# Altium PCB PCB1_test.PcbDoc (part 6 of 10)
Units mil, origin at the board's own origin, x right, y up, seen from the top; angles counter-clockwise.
Board outline 6690 x 6690 mil, 6 copper layers (Layer 1 - Top Layer, Layer 2 - GND, Layer 3 - PWR, Layer 4 - Signal, Layer 5 - GND, Layer 6 - Bottom Layer), stack 80.244 mil thick; 821 components, 458 nets, 3752 pads, 1525 vias.
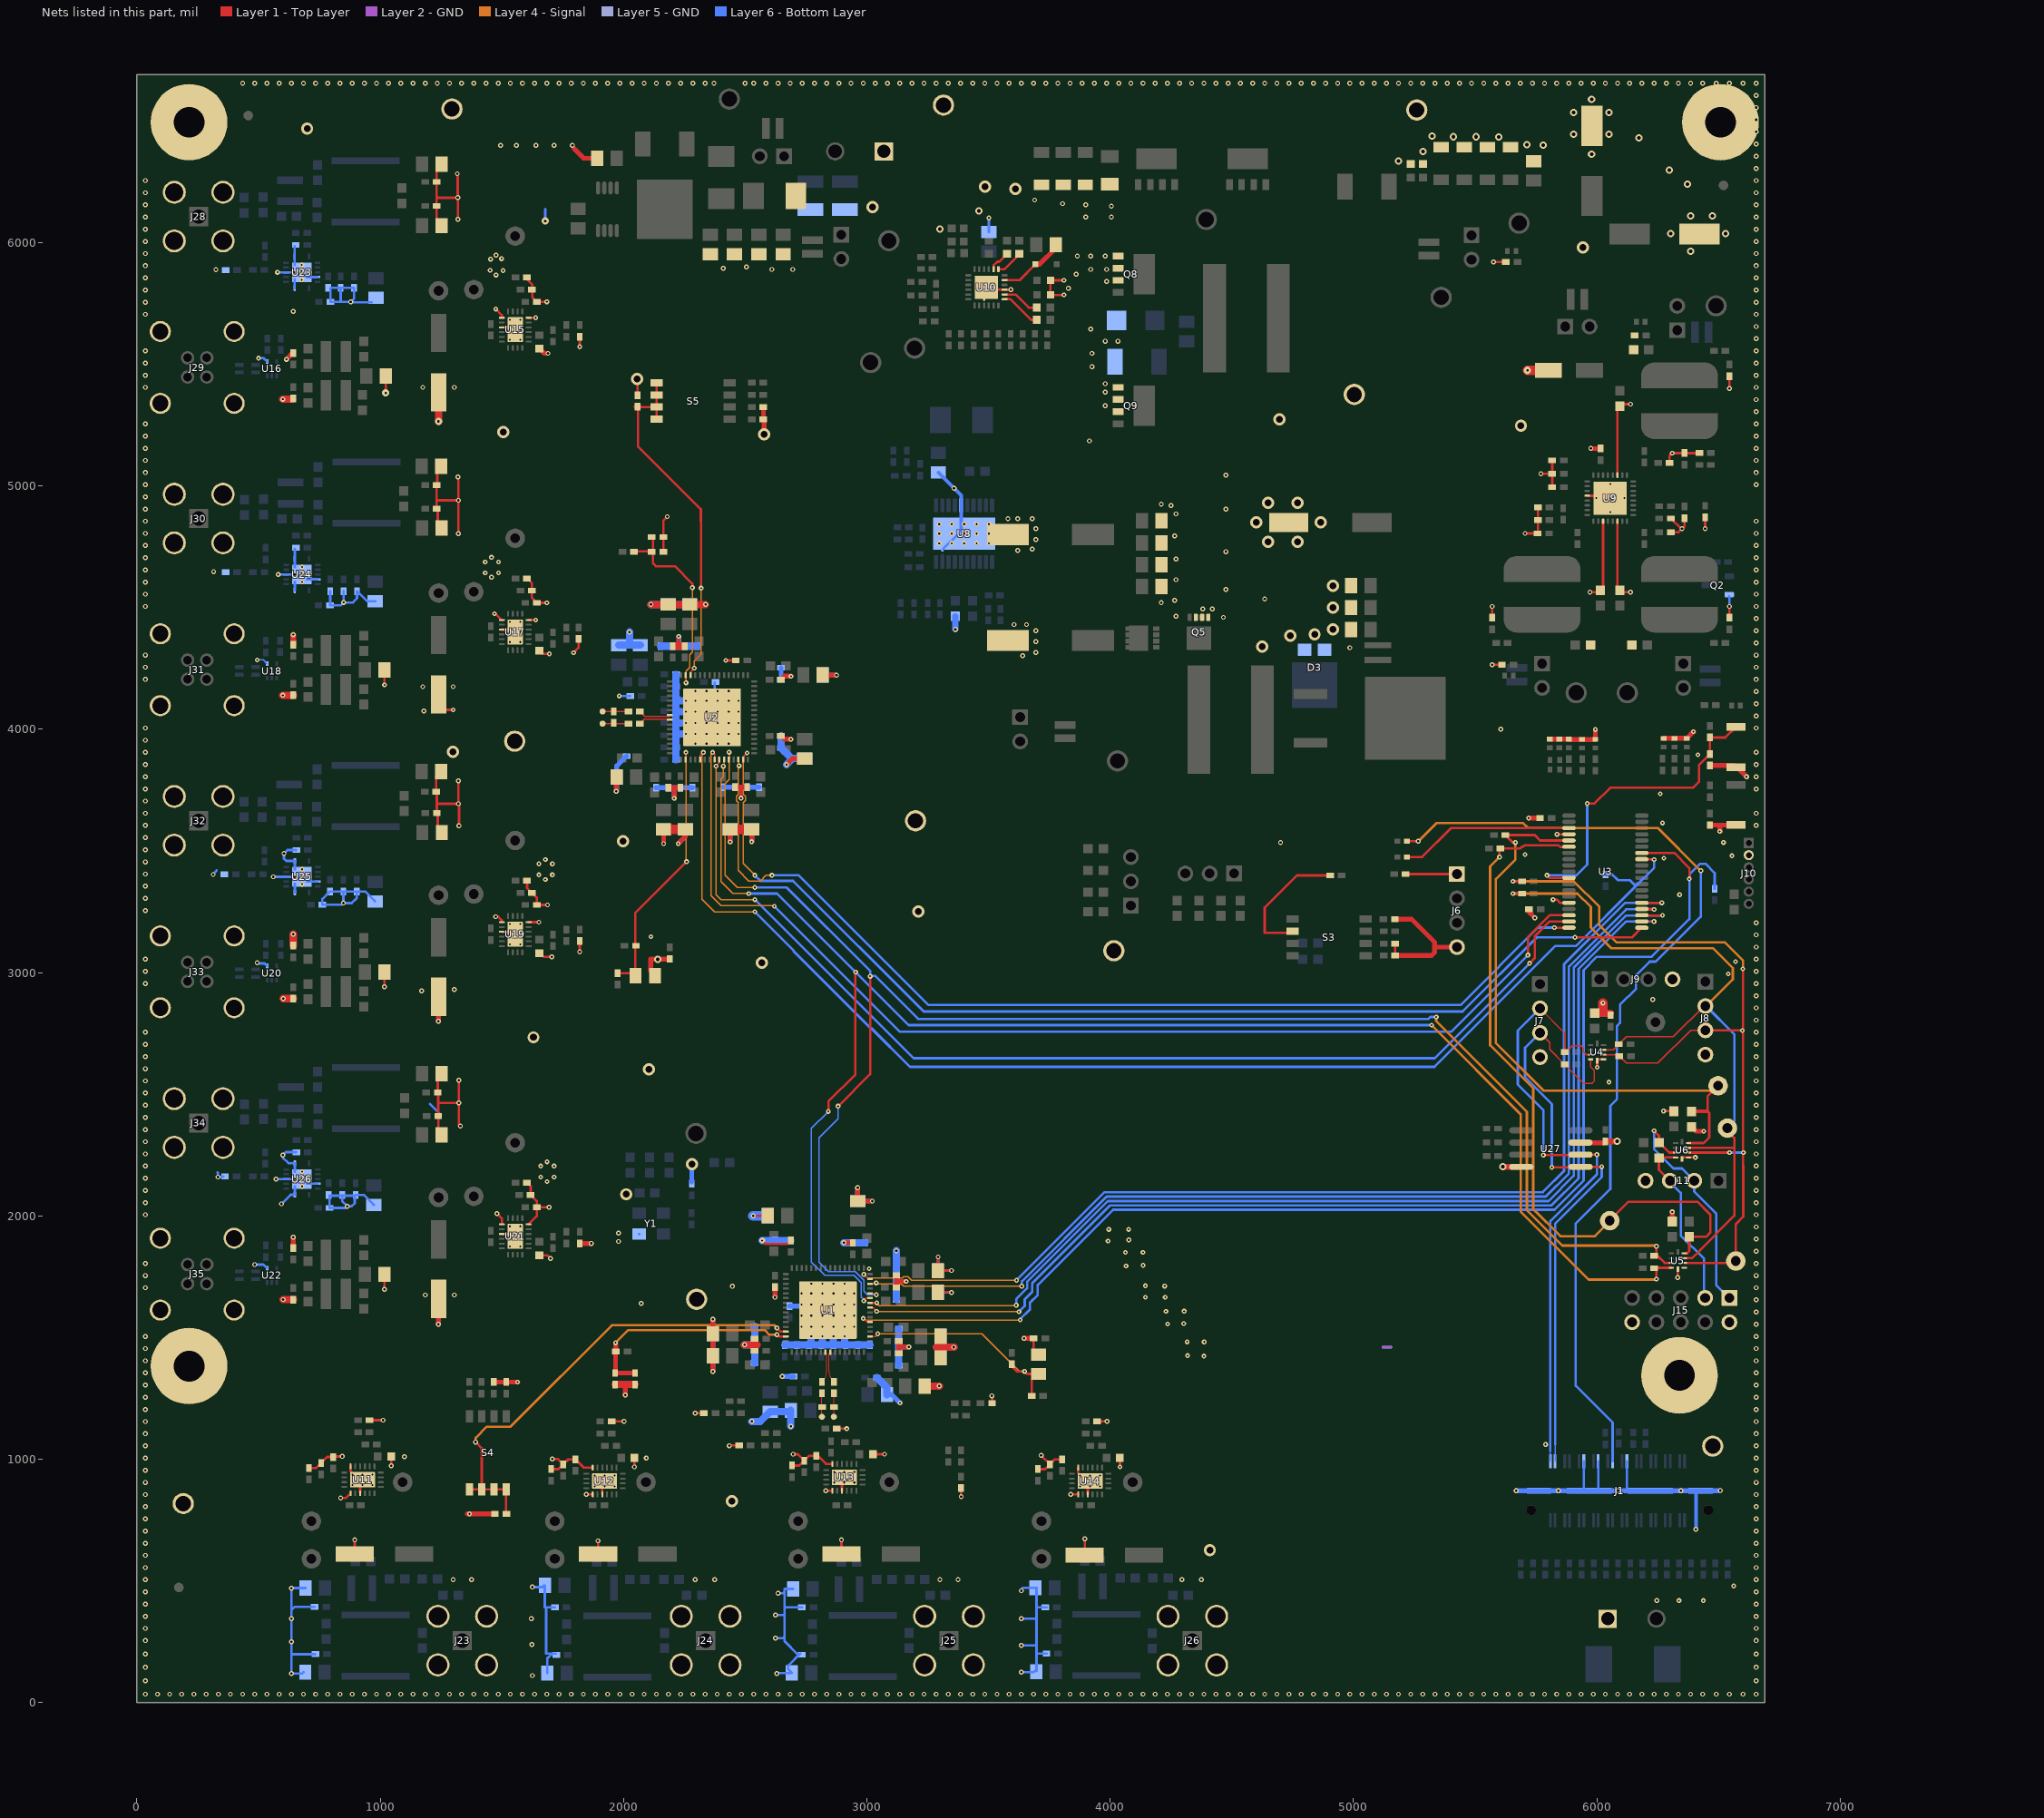
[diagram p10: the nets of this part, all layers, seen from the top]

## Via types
v1: diameter 20, hole 10, Layer 1 - Top Layer to Layer 6 - Bottom Layer, tented both sides, 491 vias
v2: diameter 20, hole 10, Layer 1 - Top Layer to Layer 6 - Bottom Layer, 310 vias
v3: diameter 19.68, hole 7.87, Layer 1 - Top Layer to Layer 6 - Bottom Layer, 274 vias
v4: diameter 19.68, hole 7.87, Layer 1 - Top Layer to Layer 6 - Bottom Layer, tented both sides, 217 vias
v5: diameter 50, hole 28, Layer 1 - Top Layer to Layer 6 - Bottom Layer, 101 vias
v6: diameter 30, hole 15, Layer 1 - Top Layer to Layer 6 - Bottom Layer, 73 vias
v7: diameter 22, hole 10, Layer 1 - Top Layer to Layer 6 - Bottom Layer, 36 vias
v8: diameter 30, hole 10, Layer 1 - Top Layer to Layer 6 - Bottom Layer, 14 vias
v9: diameter 19.68, hole 7.87, Layer 1 - Top Layer to Layer 6 - Bottom Layer, tented bottom, 4 vias
v10: diameter 30, hole 10, Layer 1 - Top Layer to Layer 6 - Bottom Layer, tented both sides, 2 vias
v11: diameter 40, hole 10, Layer 1 - Top Layer to Layer 6 - Bottom Layer, 1 vias
v12: diameter 23.62, hole 7.87, Layer 1 - Top Layer to Layer 6 - Bottom Layer, tented both sides, 1 vias
v13: diameter 23.62, hole 7.87, Layer 1 - Top Layer to Layer 6 - Bottom Layer, 1 vias

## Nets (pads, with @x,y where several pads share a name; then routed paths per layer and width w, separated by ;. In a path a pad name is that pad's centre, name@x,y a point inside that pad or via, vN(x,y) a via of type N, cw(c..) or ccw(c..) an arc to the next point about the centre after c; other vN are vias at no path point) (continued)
GND: C1.2 C2.2 C3.2 C4.2 C5.2 C6.2 C7.2 C8.2 C9.2 C10.2 C11.2 C12.2 C13.2 C14.2 C15.2 C16.2 C17.2 C18.2 C19.2 C20.2 C21.2 C22.2 C23.2 C24.2 C25.2 C26.2 C27.2 C28.2 C29.2 C30.2 C31.2 C32.2 C33.2 C34.2 C36.2 C37.2 C38.2 C39.2 C40.2 C42.2 C43.2 C44.2 C45.2 C46.2 C47.2 C48.2 C49.2 C50.2 C51.2 C52.2 C53.2 C54.2 C55.2 C56.2 C57.2 C58.2 C59.2 C60.2 C61.2 C62.2 C63.2 C64.2 C65.2 C66.2 C67.2 C68.2 C69.2 C70.2 C71.2 C72.2 C73.2 C74.2 C75.2 C76.2 C77.2 C78.2 C79.2 C80.2 C81.2 C82.2 C83.2 C84.2 C85.2 C86.2 C87.2 C88.2 C89.2 C90.2 C91.2 C92.2 C93.2 C94.2 C95.2 C96.2 C97.2 C98.2 C99.2 C100.2 C103.2 C104.2 C105.2 C106.2 C107.2 C108.2 C109.2 C110.2 C111.2 C112.2 C113.2 C114.2 C115.2 C116.2 C117.2 C118.2 C119.2 C120.2 C121.2 C122.2 C123.2 C124.2 C125.2 C126.2 C127.2 C128.2 C129.2 C130.2 C131.2 C132.2 C133.2 C134.2 C135.2 C136.2 C138.2 C139.2 C140.2 C141.2 C142.2 C143.2 C144.2 C145.2 C146.2 C147.2 C148.2 C152.2 C156.2 C157.1 C158.2 C159.1 C161.2 C162.1 C163.1 C165.2 C166.1 C167.2 C168.2 C169.2 C170.2 C171.1 C172.2 C173.2 C174.2 C175.2 C179.1 C180.2 C181.1 C183.2 C184.2 C185.2 C186.1 C187.2 C188.2 C189.2 C190.1 C196.2 C197.2 C198.2 C199.2 C200.2 C201.2 C202.2 C203.2 C210.1 C211.1 C212.2 C213.2 C214.2 C215.2 C216.2 C217.2 C218.2 C219.2 C220.2 C221.2 C222.2 C223.2 C230.1 C231.1 C232.2 C233.2 C234.2 C235.2 C236.2 C237.2 C238.2 C239.2 C240.1 C242.2 C243.2 C246.2 C251.2 C252.2 C253.2 C254.2 C255.1 C257.2 C258.2 C261.2 C266.2 C267.2 C268.2 C269.2 C270.1 C272.2 C273.2 C276.2 C281.2 C282.2 C283.2 C284.2 C285.1 C287.2 C288.2 C291.2 C296.2 C297.2 C298.2 C299.2 C300.2 C301.2 C302.2 C303.2 C304.2 C305.2 C306.2 C307.2 C308.2 C309.2 C310.2 C311.2 C312.2 C313.2 C_PVIN1.2 C_PVIN2.2 C_PVIN3.2 C_VIN1.2 D2.1 D3.1 D3.2 D8.2 D11.2 D12.2 D13.1 D15.1 D16.2 D17.2 D18.1 D19.1 H1.1 H2.1 H3.1 H4.1 J1.12 J1.16 J1.24 J1.MP1 J1.MP2 J1.MP3 J1.MP4 J6.4 J7.4 J8.4 J9.4 J10.2 J11.4 J14.1 J15.2 J15.10 J23.MH1 J23.MH2 J23.MH3 J23.MH4 J24.MH1 J24.MH2 J24.MH3 J24.MH4 J25.MH1 J25.MH2 J25.MH3 J25.MH4 J26.MH1 J26.MH2 J26.MH3 J26.MH4 J28.MH1 J28.MH2 J28.MH3 J28.MH4 J29.MH J30.MH1 J30.MH2 J30.MH3 J30.MH4 J31.MH J32.MH1 J32.MH2 J32.MH3 J32.MH4 J33.MH J34.MH1 J34.MH2 J34.MH3 J34.MH4 J35.MH J40.1 NT1.1 NT2.2 Q2.2 Q5.1 Q5.2 Q5.3 Q8.1 Q8.2 Q8.3 Q9.1 Q9.2 Q9.3 R25.1 R27.2 R28.2 R30.1 R38.1 R40.2 R41.2 R43.1 R65.1 R70.2 R87.1 R88.2 R90.1 R95.1 R96.1 R99.1 R100.1 R101.1 R120.1 R121.2 R122.1 R132.1 R133.1 R142.1 R143.1 R144.1 R145.1 R146.1 R147.1 R152.1 R153.1 R162.1 R163.1 R164.1 R165.1 R166.1 R167.1 R179.1 R180.1 R181.1 R182.1 R183.1 R184.1 R193.1 R194.1 R195.1 R196.1 R197.1 R198.1 R207.1 R208.1 R209.1 R210.1 R211.1 R212.1 R221.1 R222.1 R223.1 R224.1 R225.1 R226.1 R231.1 R232.1 R235.2 R236.1 R237.1 R240.2 R241.1 R242.1 R243.2 R246.1 R247.1 S1.2 S2.2 TP12.1 TP15.1 TP40.1 TP41.1 TP42.1 TP43.1 TP44.1 TP52.1 TP53.1 TP54.1 U1.65 U2.65 U3.4 U3.15 U4.5 U4.6 U5.5 U5.6 U6.5 U6.6 U8.15 U8.21@3399.84,4803.86 U9.4 U9.11 U9.14 U9.27 U9.33 U10.9 U10.25@3491.38,5816.38 U11.1 U11.3 U11.16 U11.21@927.56,915.87 U12.1 U12.3 U12.16 U12.21@1922.56,910.87 U13.1 U13.3 U13.16 U13.21@2907.56,925.87 U14.1 U14.3 U14.16 U14.21@3917.56,910.87 U15.1 U15.3 U15.16 U15.21@1555,5642 U16.4 U17.1 U17.3 U17.16 U17.21@1555,4400 U18.4 U19.1 U19.3 U19.16 U19.21@1555,3158 U20.4 U21.1 U21.3 U21.16 U21.21@1555,1916 U22.4 U23.5 U23.8 U23.11 U23.14 U23.15 U24.5 U24.8 U24.11 U24.14 U24.15 U25.5 U25.8 U25.11 U25.14 U25.15 U26.5 U26.8 U26.11 U26.14 U26.15 U27.4 U27.7 Y1.2 | length 27237.1
  Layer 1 - Top Layer w10: R146.1@707.56,964.49 737.56,964.49 C214.2@757.56,984.49 782.56,1009.49 R144.1@807.56,1009.49 809.93,1011.87 v2(844.56,1011.87) ; v1(837.56,840.87) 858.46,840.87 U11.1@878.34,860.75 ; U11.16@878.34,970.98 878.34,951.65 U11.21@914.13,915.87 ; C212.2@895.51,610.87 v2(895.51,668.82) ; U11.3@917.71,860.75 U11.21@917.71,906.02 ; R142.1@956.18,1160.87 v2(1012.56,1160.87) ; v4(1017.91,4182.09) C258.2@1017.91,4243.62 ; v2(1018,1698) C288.2@1018,1760 ; v2(1018,2942) C273.2@1018,3002 ; v8(1023,5382) C243.2@1023,5452.38 ; v2(1045.12,973.31) C210.1@1045.12,1010.87 ; C266.2@1230.38,3744.62 1233,3742 1233,3697 ; C266.2@1230.38,3748.62 1230.38,3805.62 1250.38,3825.62 C267.2@1250.38,3826.62 ; C236.2@1232.62,6249.5 1232.62,6294.12 C237.2@1245,6306.5 ; C268.2@1233,3655.62 1233,3697 ; C251.2@1235,5003.5 1232.62,5001.12 C253.2@1232.62,4906.5 1237,4902.12 C254.2@1237,4840.5 ; C251.2@1235,5008.5 1235,5064.5 C252.2@1251,5080.5 ; 1235,6187 1238,6184 v2@1320,6184 ; 1236,4942 1237,4941 v2(1321,4941) 1321,5036 v2(1320,5037) ; C268.2@1236.38,3657.62 1236.38,3599.62 1253.38,3582.62 C269.2@1253.38,3575.62 ; C281.2@1236.62,2508 1236.62,2563.23 C282.2@1255,2581.61 ; C236.2@1237,6251.5 1232.62,6247.12 C238.2@1232.62,6150.5 1232.62,6100.88 C239.2@1251,6082.5 ; 1238,2464.61 1238.61,2464 ; C281.2@1238,2505.61 1238.62,2504.99 1238.62,2464 ; C283.2@1238.62,2411 1238.62,2464 ; C283.2@1240,2407.61 1240,2360.61 1253,2347.61 C284.2@1253,2333 ; C257.2@1240,4142.95 1240,4080 v4(1300,4080) ; v2@1317,6284 1319,6282 1319,6199 1320,6198 v2@1320,6184 ; v2@1320,4940 1324,4936 1321,4933 v2(1321,4804) ; v2(1320,6096) v2@1320,6184 ; v2@1321,3791 v2(1321,3694) v2@1320,3694 ; v2@1323,2465.61 v2(1323,2558) ; v2(1324,3603) 1324,3690 v2@1320,3694 ; v2@1327,2366.61 1323,2370.61 v2(1323,2464) 1238.62,2464 ; v4(1470,4475) 1474.1,4475 U17.1@1499.88,4449.21 ; v1(1475,3230) 1485,3230 1499.88,3215.12 U19.1@1499.88,3207.21 ; v4(1475,5727) 1499.88,5702.12 U15.1@1499.88,5691.21 ; v1(1480,2010) 1499.88,1990.12 U21.1@1499.88,1965.21 ; U21.3@1499.88,1925.84 U21.21@1545.16,1925.84 ; U19.3@1499.88,3167.84 U19.21@1545.16,3167.84 ; U17.3@1499.88,4409.84 U17.21@1545.16,4409.84 ; U15.3@1499.88,5651.84 U15.21@1545.16,5651.84 ; R225.1@1603.62,2136 1618.62,2121 C291.2@1618.62,2086 1643.62,2061 R222.1@1643.62,2036 ; R209.1@1603.62,3378 1603.62,3348 C276.2@1623.62,3328 1643.62,3308 R208.1@1643.62,3278 v2(1688,3278) ; R197.1@1603.62,4620 1623.62,4600 C261.2@1623.62,4570 1623.62,4540 R194.1@1643.62,4520 v4(1685,4520) ; R181.1@1603.62,5857 1603.62,5848.88 1625,5827.5 1625,5775.62 R180.1@1643.62,5757 v4(1685,5757) ; U21.16@1610.12,1965.21 1643.62,1998.72 R222.1@1643.62,2036 ; U19.16@1610.12,3207.21 v2(1652.21,3207.21) ; U17.16@1610.12,4449.21 v4(1639.21,4449.21) ; U15.16@1610.12,5691.21 v4(1639.21,5691.21) ; C285.1@1655,1838.44 1686.56,1838.44 v2(1700,1825) ; C270.1@1655,3080.44 1655.99,3080.44 1671.43,3065 v2(1705,3065) ; C255.1@1655,4322.44 1655.99,4322.44 1668.43,4310 v4(1695,4310) ; v2(1694,2036) R222.1@1643.62,2036 ; R147.1@1702.56,959.49 1732.56,959.49 C215.2@1752.56,979.49 ; v2(1707.56,1000.87) 1731.18,1000.87 C215.2@1752.56,979.49 ; v4(1795,4315) 1815,4335 R193.1@1815,4371.38 ; v2(1820,3085) R207.1@1820,3129.38 ; v4(1820,5572) R179.1@1820,5613.38 ; v1(1847.68,855.75) U12.1@1873.35,855.75 ; U12.16@1873.35,965.99 1836.06,965.99 R145.1@1802.56,999.49 1772.56,999.49 C215.2@1752.56,979.49 ; C213.2@1895.51,610.87 v2@1895.51,663.82 ; U12.3@1912.72,855.75 U12.21@1912.72,901.03 ; R143.1@1951.18,1155.87 v2(2002.56,1155.87) ; v2(2045.12,968.43) C211.1@2045.12,1005.87 ; C95.2@2053.7,5368.79 C95.2@2057.74,5372.83 v5@2057.74,5439.2 ; C85.2@2163.62,4730 R38.1@2163.62,4790 2163.62,4857.31 v2(2180,4873.69) ; v2@2296,1188 cw(c2298.41,1185.59) 2298.41,1189 R132.1@2330.38,1189 ; v4(2420,4283) C72.2@2461.38,4283 ; v2@2437,1057 R133.1@2475.38,1057 ; v2(2532.56,2000.87) C21.2@2592.56,2000.87 ; v13(2570.18,1899.49) 2585.32,1884.35 2672.42,1884.35 C25.2@2687.56,1899.49 ; R166.1@2692.56,974.49 2722.56,974.49 C234.2@2742.56,994.49 ; v2(2697.56,1020.87) 2716.18,1020.87 C234.2@2742.56,994.49 ; v1(2831.73,870.75) U13.1@2858.35,870.75 ; U13.16@2858.35,980.98 2832.44,980.98 2798.94,1014.49 R164.1@2792.56,1014.49 2762.56,1014.49 C234.2@2742.56,994.49 ; R162.1@2876.18,1125.87 v4(2917.56,1125.87) ; C232.2@2895.51,610.87 v2(2895.51,668.82) ; U13.3@2897.72,870.75 U13.21@2897.72,916.02 ; C230.1@3025.12,1020.87 v2(3072.56,1020.87) ; C1.2@3291.56,1686.87 3346.56,1686.87 v2(3347.56,1685.87) ; v2(3292.56,1831.87) 3292.56,1775.87 v2(3347.56,1775.87) ; v2@3387,848 R152.1@3387,881.38 ; U10.25@3501.22,5806.54 U10.9@3566.18,5806.54 v4@3591.22,5806.54 ; R153.1@3514.62,1230 3515,1230 3515,1252.38 v2@3517,1254.38 ; R30.1@3685.63,1497.08 3685.63,1451.04 C20.2@3686.92,1449.75 ; R167.1@3702.56,959.49 3732.56,959.49 C235.2@3752.56,979.49 ; v2(3716.18,1015.87) C235.2@3752.56,979.49 ; R165.1@3802.56,999.49 3772.56,999.49 C235.2@3752.56,979.49 ; v4(3810,5785) C181.1@3754.38,5785 C180.2@3754.38,5845 v4(3810,5845) ; v1(3837.68,855.75) U14.1@3868.35,855.75 ; U14.16@3868.35,965.98 3868.35,945.08 3902.56,910.87 U14.21@3917.56,910.87 ; C233.2@3895.51,610.87 v2(3895.51,672.91) ; U14.3@3907.72,855.75 U14.21@3907.72,901.02 ; R163.1@3946.18,1155.87 v2(3987.56,1155.87) ; v3(4040.12,968.43) C231.1@4040.12,1005.87 ; R243.2@5171.29,3070 R240.2@5171.29,3118.97 ; v2(5570,4265) R96.1@5609.72,4265 ; R95.1@5570,4458.62 v2(5570,4505) ; v2(5575,5920) R121.2@5626.38,5920 ; v2(5705,4805) C169.2@5756.38,4805 ; C169.2@5757.6,4806.22 C162.1@5757.6,4860 C163.1@5757.6,4911.83 ; v2(5770,5050) R99.1@5816.38,5050 ; R90.1@5816.38,4995 R99.1@5816.38,5050 ; C167.2@5816.38,5105 R99.1@5816.38,5050 ; v3(5820,3300) 5835,3300 5847.95,3287.05 U3.15@5885.39,3287.05 ; v3(5836.46,3568.54) U3.4@5885.39,3568.54 ; U9.4@5960.51,4959.84 6045.16,4959.84 v3(6055,4950) ; v2(5971.38,4563.62) 6015,4563.62 6025.47,4574.09 U9.11@6025.47,4855.51 ; v4(6000.98,2610.98) U4.5@6000.98,2637.42 ; 6006.89,2643.33 U4.6@6027.56,2643.33 ; U9.14@6084.53,4855.51 6084.53,4574.09 6095,4563.62 v2(6138.62,4563.62) ; U9.27@6084.53,5044.49 6084.53,5325.91 6095,5336.38 v2(6138.62,5336.38) ; v3(6274,2431) 6322.54,2431 C129.2@6323.37,2430.18 ; C168.2@6298.62,5095 6298.62,5123.84 v4(6309.78,5135) C157.1@6360,5135 C159.1@6420,5135 ; C170.2@6303.62,4810 6335,4810 v2(6350,4825) ; C171.1@6308.35,4866.65 C171.1@6303.62,4866.65 6345.28,4825 v2(6350,4825) ; v2(6332.69,1747.33) U5.5@6332.69,1781.2 ; 6355.91,2240.47 U6.6@6376.57,2240.47 v4(6404.53,2240.47) ; C166.1@6360,4868.03 6360,4835 v2(6350,4825) ; v2(6445,4825) R100.1@6445,4871.38 ; R101.1@6545,4458.62 v2(6545,4505) ; v2(6545,5400) R87.1@6545,5451.38 ; 1233,3697 1236,3694 v2@1320,3694
  Layer 1 - Top Layer w15: 2227,4343.62 v4(2227,4382) ; v4(2483,3717) 2483,3761.38
  Layer 1 - Top Layer w20: v4(615,5520) 641,5546 R183.1@643,5546 ; R224.1@643,1868.62 v2(643,1913) ; v2(1240,1555) C287.2@1240,1658.95 ; v2(1240,2800) C272.2@1240,2900.95 ; v4@1357.83,776 C26.2@1466.43,776 ; R27.2@1467.42,1317.49 R28.2@1518,1317.49 v4(1565.16,1317.49) ; C240.1@1655,5564.44 1674.69,5544.76 v2(1689.76,5544.76) ; 1798.27,6384.83 1836.62,6346.48 C132.2@1892.19,6346.48 ; R221.1@1820,1887.38 v2(1867.38,1887.38) ; v2(1970,3745) C87.2@1970,3802 ; v3(2007.56,1264.06) 2007.56,1307.24 ; C86.2@2112.4,3006.22 2112.4,3055 v6(2140,3055) R43.1@2185,3055 ; v2(2165,3530) C113.2@2165,3588 ; C112.2@2184,3760.38 2208.5,3760.38 ; v4(2208.5,3716.5) 2208.5,3760.38 ; v4(2225,3530) 2254,3559 C108.2@2254,3589 ; C117.2@2234,3760.38 2208.5,3760.38 ; v2(2367.56,1360.87) C42.2@2367.56,1425.87 C36.2@2367.56,1515.87 v2(2367.56,1575.87) ; v4(2438,3537) C62.2@2438,3589 ; C67.2@2458,3761.38 2483,3761.38 C122.2@2508,3761.38 ; v4(2527,3538) C118.2@2527,3589 ; R40.2@2574.93,5324.2 R41.2@2574.93,5274.2 2578.52,5270.62 v5(2578.52,5211.46) ; v2(2622.56,1665.87) C11.2@2622.56,1707.24 ; C73.2@2647.62,3973 2661.62,3959 v4(2688,3959) ; C84.2@2647.62,4204 2661.71,4218.09 v4(2688.37,4218.09) ; v4(2670,3855) 2695,3880 C68.2@2745,3880 ; C80.2@2818,4223.31 2819,4222.31 v2(2875,4222.31) ; v2(2905.56,1889.87) C12.2@2942.56,1889.49 ; v2(2962.56,2115.87) C7.2@2962.56,2060.87 v2(3022.56,2060.87) ; C6.2@3121.18,1705.87 3121.18,1730.87 ; C61.2@3121.18,1755.87 3121.18,1730.87 ; C51.2@3131.18,1435.87 3131.18,1461.87 ; C56.2@3131.18,1485.87 3131.18,1461.87 ; v3(3161.56,1730.87) 3121.18,1730.87 ; v4(3172.56,1461.87) 3131.18,1461.87 ; v4(3645.9,1497.08) R30.1@3685.63,1497.08 ; R235.2@5169.92,3220 5238,3220 5333,3125 5333,3105 ; R243.2@5171.29,3070 5320,3070 5333,3083 5333,3105 ; J6.4@5425,3105 5333,3105 ; v3(5720,3635) C125.2@5766.38,3635 ; C126.2@5721.38,3260 5721.38,3248.62 v3(5745,3225) ; D17.2@5806,3959.34 D16.2@5846,3959.34 5884.72,3959.34 D15.1@5885,3959.62 5886.28,3958.34 D18.1@5939,3958.34 D19.1@5994,3958.34 v3(5994,3999) ; U27.7@5929.09,2300.08 6028.58,2300.08 C312.2@6035.07,2306.57 ; v2(5975,5155) 5976.38,5153.62 C_VIN1.2@6015,5153.62 ; D13.1@6274.5,3962.72 D11.2@6369.5,3962.72 v3(6396.78,3990) ; C128.2@6309.69,1977.13 v4(6309.69,2016.83) ; R70.2@6389,2366.5 6407.5,2348 v3(6439,2348) ; C124.2@6465,3606.38 6505,3606.38 ; C127.2@6465,3851.38 S2.2@6564.11,3851.38 ; v3(6505,3580) 6505,3606.38 ; S1.2@6570.7,3606.38 6505,3606.38 ; S2.2@6570.98,3844.51 6575.49,3844.51 v4(6615,3805)
  Layer 1 - Top Layer w25: R196.1@642.91,4347.24 v4(642.91,4388.62) ; v6(5613,2202) U27.4@5687.5,2202 ; C312.2@6035,2306.38 v6(6083.62,2306.38)
  Layer 1 - Top Layer w30: v4(600,4140) R195.1@642.91,4140 ; v4(600,5356) R182.1@640.24,5356 ; v2(601.38,1656.38) R223.1@643,1656.38 ; v2(601.62,2893.38) R210.1@643,2893.38 ; R211.1@643,3110.62 v2(643,3158) ; v8(1240,5265) C242.2@1240,5384.95 ; C19.2@1965.75,1307.24 2007.56,1307.24 R25.1@2047.56,1307.24 ; v2(2113,4513) v2(2337,4513) ; C100.2@2207,4341.62 C107.2@2248,4341.62 ; v2(2497.56,1470.87) 2538.94,1470.87 2548.56,1470.87 ; C27.2@3237.56,1300.87 v2(3297.56,1300.87) ; 3285.56,1460.87 v2(3357.56,1460.87) ; C123.2@5990.98,2833.05 R65.1@6055.98,2833.05
  Layer 1 - Top Layer w40: C113.2@2164,3589 C108.2@2254,3589 ; C62.2@2438,3589 C118.2@2527,3589 ; v8(5715,5475) C158.2@5800.35,5475 ; 6025,2839.87 v4(6025,2875)
  Layer 2 - GND w10: 5121,1461 5155.21,1461
  Layer 5 - GND w10: 5121,1461 5155.21,1461
  Layer 6 - Bottom Layer w5: v4(495,4285) 519.84,4285 U18.4@535.32,4269.53
  Layer 6 - Bottom Layer w10: v2(314,3403) 314,3405.81 328.19,3420 ; 331.38,2178.62 333,2177 v2(333,2160) 347.76,2160 ccw(c347.76,2170.24) R226.1@355,2163 ; v2(485,1800) 520.84,1800 U22.4@535.32,1785.53 ; v2(495,3040) 497.16,3037.84 525,3037.84 U20.4@535.32,3027.53 ; v4(500,5525) 521.84,5525 U16.4@535.32,5511.53 ; v2(561,3394) U25.11@614.04,3394 v3(679,3394) ; v2(572,2152) U26.11@614.04,2152 v3(679,2152) ; v4(578,5878) U23.11@613.04,5878 v3(678,5878) ; v4(581.06,4636.06) U24.11@613.98,4636.06 v3(678.94,4636.06) ; v2(595,2050) 632.04,2087.04 U26.8@649.48,2087.04 U26.15@649.48,2122.47 ; v2(635,250) 635,195 ; v2@635,255 v2(635,345) 635,380 ; v2(635,470) 635,380 ; v2@635,475 639.04,470.96 C199.2@692.93,470.96 ; U23.8@648.48,5813.04 U23.15@648.48,5848.47 ; U23.15@648.48,5907.52 U23.14@648.48,5942.96 R231.1@648.48,5985.31 ; U24.8@649.41,4571.1 U24.15@649.41,4606.53 ; U24.15@649.41,4665.58 U24.14@649.41,4701.02 R236.1@649.41,4741.54 ; U26.15@649.48,2181.52 U26.14@649.48,2216.96 622.89,2216.96 600,2239.85 v2(600,2250) 612,2262 R246.1@655.38,2262 ; U25.8@649.48,3329.04 U25.15@649.48,3364.47 ; U25.15@649.48,3423.52 U25.14@649.48,3458.96 614.03,3458.96 605,3467.99 v2(605,3490) 619,3504 R241.1@655.38,3504 ; C197.2@685,125 680,120 v2(635,120) 635,195 ; U23.15@697.69,5858.31 U23.5@742.96,5858.31 ; U24.15@698.62,4616.37 U24.5@743.9,4616.37 ; U26.15@698.69,2132.31 U26.5@743.96,2132.31 ; U25.15@698.69,3374.31 U25.5@743.96,3374.31 ; C198.2@731.02,393.87 648.87,393.87 635,380 ; C196.2@733.65,199.13 639.13,199.13 635,195 ; R237.1@793.62,4510 839,4510 v4(850,4521) ; R237.1@795,4511.38 C303.2@795,4567.76 ; 838,5757.94 C298.2@838,5814.38 ; C310.2@844,2086.69 C310.2@844,2083.06 ; C306.2@849,3333.69 v2(849,3286) ; C302.2@850,4568.76 C302.2@850,4567.76 v4(850,4521) ; C309.2@899,2086.69 932.62,2086.69 C308.2@974,2045.31 ; C296.2@965,5755 875,5755 v2@876.94,5756.94 ; C304.2@979,3292.31 937.62,3333.69 C305.2@904,3333.69 ; C300.2@980,4526.38 946.38,4526.38 C301.2@905,4567.76 905,4538 888,4521 v4(850,4521) ; 1205,2460 1250,2415 ; v2(1625,475) 1673.17,475 ccw(c1673.17,481.83) C203.2@1676.93,476.13 ; C203.2@1676.93,481.41 1671.93,481.41 1676.93,476.41 C203.2@1676.93,476.13 ; C203.2@1678,477 cw(c1673.17,481.83) C203.2@1676.93,476.13 ; v8(1678.81,6088.81) 1678.81,6138 ; C201.2@1686.93,121.41 1686.93,181.41 1706.93,201.41 ; C202.2@1718.31,391.41 1681.93,391.41 ; C200.2@1721.93,201.41 1706.93,201.41 ; v3(1982,4137) C76.2@2027.38,4137 ; Y1.2@2064.1,1924.58 Y1.2@2064.1,1925.4 ; C313.2@2278.77,2138.39 C313.2@2280.57,2140.19 ; C66.2@2374.62,4193 2374.62,4169.48 v3(2386.83,4157.27) ; v2(2625,265) 2655,265 2660,270 ; v2(2625,360) 2660,360 ; v2(2630,120) 2631.92,121.92 C217.2@2691.93,121.92 2676.93,136.92 2676.93,151.92 C216.2@2726.93,201.92 ; v2(2635,450) 2655,450 2660,455 ; C219.2@2696.93,466.92 2661.93,466.92 2661.93,386.92 ; 2716.93,196.92 2661.93,251.92 2661.93,386.92 ; C218.2@2733.31,391.92 2666.93,391.92 2661.93,386.92 ; C58.2@3291.56,1774.87 3346.56,1774.87 v2(3347.56,1775.87) ; C2.2@3292.56,1685.87 v2(3347.56,1685.87) ; C58.2@3292.56,1775.87 v2(3292.56,1831.87) ; U8.21@3313.84,4740.86 U8.21@3376.84,4803.86 ; C179.1@3501.38,6043.05 v4(3501.38,6101.38) ; v2@3630,460 3641.92,471.92 C223.2@3691.93,471.92 ; v2(3635,125) 3685,125 C221.2@3690,130 ; v2(3635,235) 3690,235 ; v2(3635,345) 3690,345 ; C221.2@3696.93,130 3696.93,201.92 ; 3696.93,391.92 C222.2@3733.31,391.92 C222.2@3738.31,391.92 ; C223.2@3696.93,471.92 3696.93,201.92 ; C220.2@3738.31,201.92 3696.93,201.92 ; J1.MP2@5946.44,871.6 J1.12@5946.44,992.46 ; J1.16@6005.49,992.46 6005.49,872.54 J1.MP2@6007.23,870.8 ; 6122.23,870.8 6123.6,872.17 J1.24@6123.6,992.46 ; Q2.2@6542.57,4546.7 6545,4544.27 v2(6545,4505) ; C298.2@838,5814.38 798,5814.38 795.56,5811.94 R232.1@795.56,5756.94 v2@876.94,5756.94 ; C298.2@838,5814.38 C297.2@893,5814.38 893,5770.88 v2(879.06,5756.94) v2@876.94,5756.94 ; C310.2@844,2083.06 895.38,2083.06 895.38,2052.38 883,2040 v2(865,2040) ; C310.2@844,2083.06 792.62,2083.06 R247.1@792.62,2032.84 857.84,2032.84 v2(865,2040) ; C310.2@844,2083.06 844,2061 v2(865,2040) ; v2(849,3286) 842,3279 R242.1@762.62,3279 762.62,3302.31 C307.2@794,3333.69 C305.2@904,3333.69 ; v2(849,3286) 883,3286 904,3307 C305.2@904,3333.69 ; C203.2@1676.93,476.13 1676.93,391.41 1681.93,391.41 ; 1681.93,391.41 1681.93,201.41 1706.93,201.41
  Layer 6 - Bottom Layer w15: v4(2483,3717) 2483,3756.88 ; C83.2@2647.62,4204 2661.71,4218.09 v4(2688.37,4218.09) ; C152.2@3293.84,5055.31 v2(3358.29,4990.86) 3387.05,4962.1 U8.15@3387.05,4920 U8.21@3387.05,4816.65 ; v2(6407.23,711.8) J1.MP4@6407.23,870.8
  Layer 6 - Bottom Layer w20: v2(1970,3745) 1972,3747 C88.2@1972,3804 1972,3848.98 C89.2@2012.72,3889.7 ; C110.2@2134,3760.38 2208.5,3760.38 ; C109.2@2164,3589 2165,3588 v2(2165,3530) ; v4(2208.5,3716.5) 2208.5,3760.38 ; v4(2225,3530) 2254,3559 C114.2@2254,3589 ; 2227,4343.62 v4(2227,4382) ; C313.2@2280.57,2140.19 2280.57,2211.35 v5(2281.54,2212.31) ; C115.2@2283,3760.38 2208.5,3760.38 ; v2(2367.56,1360.87) v2(2367.56,1575.87) ; C64.2@2409,3761.38 C120.2@2557,3761.38 ; v4(2438,3537) C63.2@2438,3589 ; v4(2527,3538) C119.2@2527,3589 ; C83.2@2647.62,4204 C82.2@2647.62,4253 ; v2(2652.56,1340.87) C15.2@2698.94,1340.87 ; C5.2@2682.56,1629.49 2725.2,1629.49 v3(2731.85,1636.14) ; C81.2@2819,4223 v2@2874.31,4223 ; v2(2962.56,2115.87) C8.2@2962.56,2060.87 v2(3022.56,2060.87) ; C28.2@3082.56,1265.87 3102.56,1265.87 v4(3136.56,1231.87) ; 3132.18,1461.87 v4(3172.56,1461.87) ; v2(5668.23,870.8) J1.MP1@5761.79,870.8 v2(5842.23,870.8) J1.MP2@5969.27,870.8 6007.23,870.8 v2(6087.23,870.8) 6122.23,870.8 J1.MP3@6219.27,870.8 v2(6344.99,870.8) 6407.23,870.8 J1.MP4@6426.75,870.8 v2@6506.23,870.8
  Layer 6 - Bottom Layer w25: v2(3363.84,4410.86) C148.2@3363.84,4464.36
  Layer 6 - Bottom Layer w30: C74.2@1980,4346 2024.5,4346 ; v2(2024.5,4399.5) 2024.5,4346 ; C75.2@2069,4346 2024.5,4346 ; v2(2113,4513) C97.2@2183,4513 C104.2@2272,4513 ; C98.2@2152,4341.62 C105.2@2303,4341.62 ; C90.2@2215.62,3875.5 C91.2@2215.62,3925.5 C79.2@2215.62,3975.5 C93.2@2215.62,4025.5 C92.2@2215.62,4075.5 C78.2@2215.62,4125.5 C94.2@2215.62,4225.5 ; C93.2@2216.29,4026.17 v3(2255.73,4026.17) ; C92.2@2219.29,4071.83 v3(2255.73,4071.83) ; C79.2@2220.62,3980.5 v3(2255.73,3980.5) ; C78.2@2223.62,4117.5 v3(2255.73,4117.5) ; v2(2497.56,1470.87) 2538.94,1470.87 ; v2(2527.56,1155.87) 2562.56,1155.87 C13.2@2602.56,1195.87 C14.2@2682.56,1195.87 ; C38.2@2538.94,1395.87 C44.2@2538.94,1545.87 ; v13(2570.18,1899.49) C24.2@2687.56,1899.49 ; C71.2@2647.62,3973 C70.2@2647.62,3923 2690.62,3880 ; C31.2@2662.56,1469.49 C17.2@2762.56,1469.49 C32.2@2812.56,1469.49 C33.2@2862.56,1469.49 C18.2@2912.56,1469.49 C34.2@2962.56,1469.49 C30.2@3012.56,1469.49 ; v4(2670,3855) 2690.62,3875.62 2690.62,3880 ; v2(2687.56,1135.87) C14.2@2687.56,1200.87 ; C69.2@2745,3880 2690.62,3880 ; C17.2@2771.61,1478.54 v9(2771.61,1505.04) ; C32.2@2817.28,1474.21 v9(2817.28,1505.04) ; C33.2@2862.95,1469.88 v9(2862.95,1505.04) ; v2(2905.56,1889.87) 2942.56,1889.71 C9.2@2992.56,1889.49 ; C18.2@2908.62,1473.42 v9(2908.62,1505.04) ; C29.2@3041.18,1335.87 3082.56,1294.49 C28.2@3082.56,1265.87 ; C3.2@3121.18,1655.87 C60.2@3121.18,1755.87 C59.2@3121.18,1805.87 v2(3121.18,1857.24) ; C49.2@3131.18,1385.87 3131.18,1460.87 ; C50.2@3131.18,1435.87 3131.18,1460.87 ; C55.2@3131.18,1485.87 3131.18,1460.87 ; C54.2@3131.18,1535.87 3131.18,1460.87 ; 3285.56,1460.87 3302.56,1460.87 ; C48.2@3302.56,1416.87 3302.56,1460.87 ; C53.2@3302.56,1504.87 3302.56,1460.87 ; v2(3357.56,1460.87) 3302.56,1460.87
  Layer 6 - Bottom Layer w40: v2(2532.56,2000.87) C22.2@2592.56,2000.87
  other v1: 35,35 85,35 135,35 185,35 235,35 285,35 335,35 385,35 435,35 485,35 535,35 585,35 635,35 685,35 735,35 785,35 835,35 885,35 935,35 985,35 1035,35 1085,35 1135,35 1185,35 1235,35 1285,35 1335,35 1385,35 1435,35 1485,35 1535,35 1585,35 1635,35 1685,35 1735,35 1785,35 1835,35 1885,35 1935,35 1985,35 2035,35 2085,35 2135,35 2185,35 2235,35 2285,35 2335,35 2385,35 2435,35 2485,35 2535,35 2585,35 2635,35 2685,35 2735,35 2785,35 2835,35 2885,35 2935,35 2985,35 3035,35 3085,35 3135,35 3185,35 3235,35 3285,35 3335,35 3385,35 3435,35 3485,35 3535,35 3585,35 3635,35 3685,35 3735,35 3785,35 3835,35 3885,35 3935,35 3985,35 4035,35 4085,35 4135,35 4185,35 4235,35 4285,35 4335,35 4385,35 4435,35 4485,35 4535,35 4585,35 4635,35 4685,35 4735,35 4785,35 4835,35 4885,35 4935,35 4985,35 5035,35 5085,35 5135,35 5185,35 5235,35 5285,35 5335,35 5385,35 5435,35 5485,35 5535,35 5585,35 5635,35 5685,35 5735,35 5785,35 5835,35 5885,35 5935,35 5985,35 6035,35 6085,35 6135,35 6185,35 6235,35 6285,35 6335,35 6385,35 6435,35 6490,35 6545,35 6600,35 6655,35 35,90 6655,90 35,145 6655,145 35,200 6655,200 35,255 6655,255 35,305 6655,305 35,355 6655,355 35,405 6655,405 35,455 6655,455 35,505 6655,505 35,555 6655,555 35,605 6655,605 35,655 6655,655 35,705 6655,705 35,755 6655,755 35,805 6655,805 35,855 6655,855 35,905 6655,905 35,955 6655,955 35,1005 6655,1005 1099.56,1010.87 35,1055 6655,1055 35,1105 6655,1105 35,1155 6655,1155 35,1205 6655,1205 35,1255 6655,1255 35,1305 6655,1305 35,1355 6655,1355 35,1405 6655,1405 35,1455 6655,1455 35,1505 6655,1505 6655,1555 6655,1605 6655,1655 35,1705 6655,1705 35,1755 6655,1755 35,1805 6655,1805 6655,1855 6655,1905 6655,1955 35,2005 6655,2005 35,2055 6655,2055 35,2105 6655,2105 35,2155 6655,2155 35,2205 6655,2205 35,2255 6655,2255 35,2305 6655,2305 35,2355 6655,2355 35,2405 6655,2405 35,2455 6655,2455 35,2505 6655,2505 35,2555 6655,2555 35,2605 6655,2605 35,2655 6655,2655 35,2705 6655,2705 35,2755 6655,2755 6655,2805 6655,2855 6655,2905 35,2955 6655,2955 35,3005 6655,3005 35,3055 6655,3055 6655,3105 6655,3155 6655,3205 35,3255 35,3305 35,3355 35,3405 35,3455 35,3505 35,3555 35,3605 6655,3605 35,3655 6655,3655 35,3705 35,3755 6655,3755 35,3805 6655,3805 35,3855 6655,3855 35,3905 6655,3905 35,3955 35,4005 6655,4005 6655,4055 6655,4105 6655,4155 35,4205 6655,4205 35,4255 6655,4255 35,4305 6655,4305 6655,4355 6655,4405 6655,4455 35,4505 6655,4505 35,4555 6655,4555 35,4605 6655,4605 35,4655 6655,4655 35,4705 6655,4705 35,4755 6655,4755 35,4805 6655,4805 35,4855 6655,4855 35,4905 35,4955 35,5005 6655,5005 35,5055 6655,5055 35,5105 6655,5105 35,5155 6655,5155 35,5205 6655,5205 35,5255 6655,5255 6655,5305 6655,5355 35,5405 6655,5405 35,5455 6655,5455 35,5505 6655,5505 35,5555 6655,5555 4032,5595 6655,5605 6655,5655 35,5705 6655,5705 35,5755 6655,5755 35,5805 6655,5805 3828,5813 35,5855 6655,5855 35,5905 6655,5905 35,5955 6655,5955 35,6005 6655,6005 35,6055 6655,6055 35,6105 6655,6105 35,6155 6655,6155 35,6205 6655,6205 35,6255 6655,6255 6655,6305 6655,6355 6655,6405 6655,6455 6655,6505 6655,6555 6655,6605 435,6655 485,6655 535,6655 585,6655 635,6655 685,6655 735,6655 785,6655 835,6655 885,6655 935,6655 985,6655 1035,6655 1085,6655 1135,6655 1185,6655 1235,6655 1285,6655 1335,6655 1385,6655 1435,6655 1485,6655 1535,6655 1585,6655 1635,6655 1685,6655 1735,6655 1785,6655 1835,6655 1885,6655 1935,6655 1985,6655 2035,6655 2085,6655 2135,6655 2185,6655 2235,6655 2285,6655 2335,6655 2372,6655 2500,6655 2535,6655 2585,6655 2635,6655 2685,6655 2735,6655 2785,6655 2835,6655 2885,6655 2935,6655 2985,6655 3035,6655 3085,6655 3135,6655 3185,6655 3235,6655 3285,6655 3335,6655 3385,6655 3435,6655 3485,6655 3535,6655 3585,6655 3635,6655 3685,6655 3735,6655 3785,6655 3835,6655 3885,6655 3935,6655 3985,6655 4035,6655 4085,6655 4135,6655 4185,6655 4235,6655 4285,6655 4335,6655 4385,6655 4435,6655 4485,6655 4535,6655 4585,6655 4635,6655 4685,6655 4735,6655 4785,6655 4835,6655 4885,6655 4935,6655 4985,6655 5035,6655 5085,6655 5135,6655 5185,6655 5235,6655 5285,6655 5335,6655 5385,6655 5435,6655 5485,6655 5535,6655 5585,6655 5635,6655 5685,6655 5735,6655 5785,6655 5835,6655 5885,6655 5935,6655 5985,6655 6035,6655 6085,6655 6135,6655 6185,6655 6235,6655 6285,6655 6335,6655 6385,6655 6435,6655 6490,6655 6545,6655 6600,6655 6655,6655
  other v2: 1625,111 1623,239 1621,345 3635,460 1300,505 1375,505 2295,505 2375,505 3300,505 3375,505 4295,505 4375,505 1895,665 3388,846 6507.23,871.8 2435,1056 2295,1189 3514,1261 2072.56,1640.87 1185,1675 1305,1675 2447.56,1710.87 1980,1895 1980,1930 1330,2369 6230,2890 1170,2925 1305,2930 4700,3535 1322,3788 5605,4000 1180,4075 1175,4175 1300,4175 3640,4303 3695,4315 4985,4335 3695,4360 3695,4405 3605,4430 3656.37,4430 4465,4460 4270,4465 4380,4495 4420,4495 4210,4520 4265,4530 4635,4535 4475,4575 4270,4615 316,4648 4270,4700 4475,4730 3620,4735 3680,4740 3695,4780 4265,4795 3695,4825 3580,4865 3620,4865 3680,4865 4270,4885 4475,4905 4250,4920 4210,4925 4475,5045 3915,5185 3980,5330 3980,5385 1175,5405 1305,5405 3980,5420 3925,5490 3925,5545 3980,5595 3920,5645 643,5717 3985,5840 3860,5870 325,5889 2610,5890 2695,5890 3920,5890 3985,5890 2410,5895 2505,5900 3865,5945 3920,5945 3980,5945 3900,6105 4005,6105 4005,6150 3900,6155 3805,6160 3690,6175 1319,6185 1317,6283 1495,6400 1560,6400 1640,6400 1715,6400 1790,6400
  other v3: 6562.23,479.48 1881.22,889.21 1922.56,889.21 1963.9,889.21 3876.22,889.21 3917.56,889.21 3958.9,889.21 886.22,894.21 927.56,894.21 968.89,894.21 2866.22,904.21 2907.56,904.21 2948.9,904.21 1881.22,932.52 1922.56,932.52 1963.9,932.52 3876.22,932.52 3917.56,932.52 3958.9,932.52 886.22,937.52 927.56,937.52 968.89,937.52 2866.22,947.52 2907.56,947.52 2948.9,947.52 4384.81,1424.08 4317.86,1425.8 4315.72,1482.44 4386.52,1482.01 2731.85,1544.8 2771.61,1544.8 2817.28,1544.8 2862.95,1544.8 2908.62,1544.8 2948.39,1544.8 4236.33,1555.82 4301.99,1557.97 2731.85,1590.47 2771.61,1590.47 2817.28,1590.47 2862.95,1590.47 2908.62,1590.47 2948.39,1590.47 4229.22,1608.23 4304.13,1608.6 2771.61,1636.14 2817.28,1636.14 2862.95,1636.14 2908.62,1636.14 2948.39,1636.14 4145,1666 4226,1666 2731.85,1681.81 2771.61,1681.81 2817.28,1681.81 2862.95,1681.81 2908.62,1681.81 2948.39,1681.81 4224,1712 4145,1713 2771.61,1721.57 2817.28,1721.57 2862.95,1721.57 2908.62,1721.57 4064.96,1794.29 4135.06,1797.42 4062.99,1850.39 4134.84,1850.39 1533.35,1874.66 1576.65,1874.66 3991.14,1896.65 4076.77,1901.57 1533.35,1916 1576.65,1916 3994.09,1944.88 4075.79,1944.88 1533.35,1957.34 1576.65,1957.34 679,2121.49 648.49,2152 709.51,2152 679,2182.51 6050,2550 6540,2995 6570,3045 1533.35,3116.66 1576.65,3116.66 1533.35,3158 1576.65,3158 1533.35,3199.34 1576.65,3199.34 6340,3320 679,3363.49 648.49,3394 709.51,3394 679,3424.51 6275,3470 6555,3480 5705,3485 6520,3535 6270,3615 6260,3735 6415,3895 2295.5,3940.73 2341.17,3940.73 2386.83,3940.73 2432.5,3940.73 2295.5,3980.5 2341.17,3980.5 2386.83,3980.5 2432.5,3980.5 2472.27,3980.5 2295.5,4026.17 2341.17,4026.17 2386.83,4026.17 2432.5,4026.17 2472.27,4026.17 2295.5,4071.83 2341.17,4071.83 2386.83,4071.83 2432.5,4071.83 2472.27,4071.83 2295.5,4117.5 2341.17,4117.5 2386.83,4117.5 2432.5,4117.5 2472.27,4117.5 2295.5,4157.27 2341.17,4157.27 2432.5,4157.27 1533.35,4358.66 1576.65,4358.66 1533.35,4400 1576.65,4400 1533.35,4441.34 1576.65,4441.34 678.94,4605.55 648.43,4636.06 709.45,4636.06 678.94,4666.57 3348.66,4764.49 3399.84,4764.49 3451.02,4764.49 3348.66,4803.86 3399.84,4803.86 3451.02,4803.86 3348.66,4843.23 3399.84,4843.23 3451.02,4843.23 6055,4891.93 5996.93,4950 6113.07,4950 6055,5008.07 1533.35,5600.66 1576.65,5600.66 1533.35,5642 1576.65,5642 1533.35,5683.34 1576.65,5683.34 678,5847.49 647.49,5878 708.51,5878 678,5908.51
  other v4: 6337.23,419.48 6437.23,419.48 6246.17,419.52 1367.25,775.69 2093.56,1004.87 5789.37,1061.02 3009.21,1783.15 1686.28,2140.89 1660,2160 1715,2160 1660,2205 1715,2205 1686.28,2222.55 2112.4,3147.6 1679.1,3382.89 1652.72,3401.78 1707.72,3401.78 1652.72,3446.78 1707.72,3446.78 1679.1,3464.55 1457.45,4624.96 1431.72,4642.78 1486.72,4642.78 1431.72,4687.78 1486.72,4687.78 1457.45,4706.62 3297.48,4764.49 3502.2,4764.49 3297.48,4803.86 3502.2,4803.86 3297.48,4843.23 3502.2,4843.23 3592,5807 1476.18,5866.89 1505,5885 1452.15,5885.7 1454,5932 1499,5934 1476.18,5948.55
  other v5: 4409.45,626.97 2445.56,827.87 2011,2089 2104,2603 1630,2734 2569,3041 3212.33,3251.09 1998,3540 1299,3908 4625,4340 4740,4385 4840,4390 4915,4410 4915,4500 4915,4590 4649.17,4770 4770,4770 4600,4850 4865,4850 4649.17,4930 4770,4930 1506,5222 5688,5248 4696,5274 2056.31,5439.2 5943,5980 3023.62,6145.67 3610,6220 3485,6230 700,6469
  other v6: 6385,5965 6304,6037 6528,6037 3300,6055 6386,6110 6474,6110 3460,6130 6373,6241 6297,6298 5185,6335 5978,6364 5285,6375 5779,6401 5713,6402 6172,6430 5597,6434 5410,6435 5503,6435 5323,6437 6050,6445 5905,6446 5905,6534 6050,6535 5978,6588
GPIO0_0: U2.9 U3.17 | length 4624.1
  Layer 1 - Top Layer w5: v4(2366,3905) 2373.84,3897.16 U2.9@2373.84,3875.77
  Layer 1 - Top Layer w10: v3(5716.54,3071.85) 5716.54,3146.54 5805.87,3235.87 U3.17@5885.39,3235.87
  Layer 4 - Signal w5: v4(2366,3905) 2359,3898 2359,3316 2400,3275 2615.17,3275 cw(c2615.17,3268.17) v4(2620,3273)
  Layer 6 - Bottom Layer w10: v4(2620,3273) 3136,2757 5401.69,2757 v3(5716.54,3071.85)
GPIO0_1: U2.10 U3.18 | length 4630.2
  Layer 1 - Top Layer w5: v4(2380.41,3849) 2393.53,3862.12 U2.10@2393.53,3875.77
  Layer 1 - Top Layer w10: v3(5723.43,3038.39) 5745,3059.96 5745,3150 5805.28,3210.28 U3.18@5885.39,3210.28
  Layer 4 - Signal w5: v4(2380.41,3849) 2380.41,3319.59 2400,3300 v4(2540,3300)
  Layer 6 - Bottom Layer w10: v4(2540,3300) 3191.78,2648.22 5333.26,2648.22 v3(5723.43,3038.39)
GPIO0_2: U2.14 U3.19 | length 4257.7
  Layer 1 - Top Layer w5: U2.14@2472.27,3875.77 2472.27,3852.73 v4(2475,3850)
  Layer 1 - Top Layer w10: v3@5825.31,3184.69 U3.19@5885.39,3184.69
  Layer 4 - Signal w5: v4(2475,3850) 2472,3847 2472,3733 2464,3725 2464,3706 2472,3698 2472,3420 2515,3377 2563,3377 2586,3400 v4(2610,3400)
  Layer 6 - Bottom Layer w10: v4(2610,3400) 2720,3400 3253,2867 5439.83,2867 5757.83,3185 v3(5825,3185)
GPIO0_3: U2.15 U3.20 | length 4590.2
  Layer 1 - Top Layer w5: U2.15@2491.95,3875.77 2491.95,3886.95 v4(2508,3903)
  Layer 1 - Top Layer w10: v3(5910,3145) 6144.92,3145 U3.20@6184.61,3184.69
  Layer 4 - Signal w5: v4(2508,3903) 2492,3887 2492,3733 2501,3724 2501,3708 2492,3699 2492,3448 v4(2540,3400)
  Layer 6 - Bottom Layer w10: v4(2540,3400) 2563,3377 2697,3377 3234,2840 5448.27,2840 5753.27,3145 v3(5910,3145)
GPIO1_0: U1.9 U3.21 | length 4483
  Layer 1 - Top Layer w5: U1.9@3013.35,1623.15 3025.28,1623.15 v4(3040.12,1608.31) ; U3.21@6184.61,3210.28 v3(6234.72,3210.28)
  Layer 4 - Signal w5: v4(3040.12,1608.31) 3042.12,1606.3 v3(3625,1606.3)
  Layer 6 - Bottom Layer w10: v3(3625,1606.3) 3648.62,1629.92 3648.62,1657.48 3679.63,1688.48 3679.63,1722.93 4000,2043.31 5813.31,2043.31 5925,2155 5925,3015 6120.28,3210.28 v3(6234.72,3210.28)
GPIO1_1: U1.10 U3.22 | length 4545.3
  Layer 1 - Top Layer w10: U1.10@3013.35,1642.83 v4(3041.03,1642.83) ; U3.22@6184.61,3235.87 6185.47,3235 v3(6270,3235)
  Layer 4 - Signal w5: v4(3041.03,1642.83) 3054.15,1629.72 3055.34,1630.91 v3@3614.17,1630.91
  Layer 6 - Bottom Layer w10: v3@3614.17,1630.91 3614.17,1658.46 3658.92,1703.21 3658.92,1729.79 3990.16,2061.02 5801.02,2061.02 5905,2165 5905,3020 6120,3235 v3(6270,3235)
  other v3: 3614,1633
GPIO1_2: U1.14 U3.23 | length 4432
  Layer 1 - Top Layer w5: U1.14@3013.35,1721.57 3035.27,1721.57 v4(3038.56,1724.87)
  Layer 1 - Top Layer w10: U3.23@6184.61,3261.46 6233.54,3261.46 v3(6235,3260)
  Layer 4 - Signal w5: v4(3038.56,1724.87) 3042.12,1721.31 3141.33,1721.31 3151.77,1710.87 3171.56,1710.87 3173.56,1712.87 3174.81,1711.61 v3(3636.81,1711.61)
  Layer 6 - Bottom Layer w10: v3(3636.81,1711.61) 3636.81,1731.3 3985.24,2079.72 5789.72,2079.72 5885,2175 5885,3025 6120,3260 v3(6235,3260)
GPIO1_3: U1.15 U3.24 | length 4550.8
  Layer 1 - Top Layer w5: v4(2987.56,1759.87) 3006.17,1741.26 U1.15@3013.35,1741.26
  Layer 1 - Top Layer w10: U3.24@6184.61,3287.05 v3(6267.05,3287.05)
  Layer 4 - Signal w5: v4(2987.56,1759.87) 3002.56,1744.87 3145.68,1744.87 3151.68,1750.87 3169.56,1750.87 3184.56,1735.87 v3(3615.16,1735.87)
  Layer 6 - Bottom Layer w10: v3(3615.16,1735.87) 3976.73,2097.44 5777.44,2097.44 5865,2185 5865,3035 6117.05,3287.05 v3(6267.05,3287.05)
HB: C178.2 D9.1 U10.11 | length 275.4
  Layer 1 - Top Layer w10: U10.11@3566.18,5845.91 3627.6,5845.91 D9.1@3693.07,5911.38 ; C178.2@3773.07,5991.38 C178.2@3776.38,5991.38
  Layer 1 - Top Layer w20: D9.1@3693.07,5911.38 3709.82,5911.38 C178.2@3773.07,5974.63 ; C178.2@3764.7,5983.01 C178.2@3773.07,5991.38
HO: R108.1 U10.13 | length 113.2
  Layer 1 - Top Layer w10: U10.13@3540.59,5891.18 3566.18,5891.18 3626.38,5951.38 R108.1@3626.38,5953.82
HOL: R109.1 U10.14 | length 90
  Layer 1 - Top Layer w10: U10.14@3520.91,5891.18 3520.91,5905.91 3536.38,5921.38 3543.94,5921.38 R109.1@3576.38,5953.82
I2C_SCL_EXT: J11.2 J15.1 R71.1 U6.3 | length 983.8
  Layer 1 - Top Layer w10: v3(6235,2350) 6254.86,2330.14 6254.86,2303.7 6298.4,2260.16 U6.3@6323.43,2260.16 ; J11.2@6400,2145 J11.2@6404.42,2140.58
  Layer 6 - Bottom Layer w10: v3(6235,2350) 6235,2275 6315,2195 6350,2195 J11.2@6400,2145 6400,2100.23 6490.14,2010.09 6490.14,1716.38 J15.1@6544.32,1662.2
I2C_SCL_SOC: J1.2 J7.2 R56.1 U4.3 U27.6 | length 2602.3
  Layer 1 - Top Layer w5: R56.1@5873.19,2672.86 5900.33,2700 5934.7,2700 5945,2689.7 5945,2675 5956.99,2663.01 U4.3@5974.41,2663.01
  Layer 1 - Top Layer w5.9: J7.2@5765.98,2852.86 5867.36,2751.48 R56.1@5867.36,2672.86 R56.1@5867.36,2669.82
  Layer 1 - Top Layer w10: v4(5780,2250) U27.6@5928.5,2250 ; U27.6@5930.5,2252 v4(6000,2252)
  Layer 6 - Bottom Layer w5.9: J1.2@5808.64,992.46 5808.64,1035.39
  Layer 6 - Bottom Layer w10: J7.2@5765.98,2852.86 5675,2761.87 5675,2540 5780,2435 v4(5780,2250) ; 5808.64,1035.39 5808.64,1978.64 6000,2170 v4(6000,2252)
I2C_SCL_UB960: R67.1 U1.12 U2.12 U5.3 | length 7002.4
  Layer 1 - Top Layer w5: U2.12@2434,3876.87 v4(2434,3906) ; U1.12@3013.35,1682.2 3033.22,1682.2 v4(3039.56,1675.87)
  Layer 1 - Top Layer w10: v4@2882.04,2451.07 3013.64,2582.67 v4(3013.64,2984.97) ; R67.1@6235.31,1836.33 R67.1@6244.69,1836.33 ; v3(6244.69,1875.63) R67.1@6244.69,1836.33 ; U5.3@6306.12,1806.79 6279.23,1806.79 6249.69,1836.33 R67.1@6244.69,1836.33
  Layer 4 - Signal w5: v4(2434,3906) 2434,3794 2417,3777 2417,3400 2467,3350 v4(2540,3350)
  Layer 4 - Signal w10: v3@5339,2817.76 v3@5339.23,2817.76 ; v3@5339.23,2817.99 v3@5339.23,2817.76 ; v3(5340,2817.76) v3@5339.23,2817.76 ; v3@6242.97,1878.31 5857.91,1878.31 5712.6,2023.62 5712.6,2427.4 5339.23,2800.77 v3@5339.23,2817.76 ; v3@6243.83,1876.5 v3(6244.69,1875.63)
  Layer 6 - Bottom Layer w5: v4@2881.35,2453.8 2881.35,2399.41 2802.56,2320.62 2802.56,1810.87 2842.56,1770.87 2952.56,1770.87 2987.56,1735.87 2987.56,1690.87 3002.56,1675.87 v4(3039.56,1675.87)
  Layer 6 - Bottom Layer w10: v4(2540,3350) 2671,3350 3013.87,3007.13 v4@3013.87,2985.95 ; v4@3013.26,2985.95 v4@3013.87,2985.95 ; v4@3013.87,2985.65 v4@3013.87,2985.95 ; v3(5340,2817.76) 5333.94,2817.76 5333.86,2817.84 5321.9,2817.84 5321.82,2817.76 5315.76,2817.76 5308,2810 3211,2810 3035.05,2985.95 v4@3013.87,2985.95
  other v4: 2881.54,2451.3
I2C_SCL_UC: J8.2 R54.1 R64.1 TP6.1 U4.8 U5.8 U6.8 | length 3205.7
  Layer 1 - Top Layer w5: U4.8@6027.56,2682.7 6067.18,2682.7 R54.1@6090.55,2706.06 6121.11,2736.63 6313.59,2736.63 J8.2@6443.04,2866.08
  Layer 1 - Top Layer w10: v4(5655,3325) R64.1@5692.6,3325 ; U5.8@6359.27,1826.47 6391.53,1826.47 6423.69,1858.63 ; U6.8@6376.57,2279.84 6564.84,2279.84 ; 6423.83,1859.47 6565,2000.64 6565,2175.89 6564.84,2279.84 ; J8.2@6445.98,2862.86 J8.2@6448.84,2860 ; TP6.1@6535,2350.79 6564.84,2320.95 6564.84,2279.84
  Layer 4 - Signal w10: v4(5655,3325) 5920,3325 5975,3270 5975,3185 6060,3100 6477.71,3100 6556.59,3021.12 6558.84,3018.87 6558.84,2971.72 J8.2@6447.39,2860.26
  Layer 6 - Bottom Layer w10: J8.2@6449.47,2861.66 6565,2746.13 6565,2389.8 TP6.1@6537.04,2361.84
I2C_SDA_EXT: J11.3 J15.3 R72.1 U6.4 | length 716.6
  Layer 1 - Top Layer w10: R72.1@6254.86,2238.7 6254.86,2190.14 J11.3@6300,2145 J11.3@6304.42,2140.58 ; R72.1@6256.63,2240.47 U6.4@6323.43,2240.47
  Layer 6 - Bottom Layer w10: J11.3@6298.14,2141.53 6344.85,2094.82 6344.85,1919.12 6440.45,1823.52 J15.3@6440.45,1669.3
I2C_SDA_SOC: J1.4 J7.3 R57.1 U4.4 U27.5 | length 2544.1
  Layer 1 - Top Layer w5.9: J7.3@5765.98,2752.86 5805.98,2712.86 5805.98,2684.23 R57.1@5867.36,2622.86 5945.21,2545 5980,2545 5989.78,2554.78 5989.78,2597.26 5974.41,2612.63 U4.4@5974.41,2643.33
  Layer 1 - Top Layer w10: v4(5815,2200) 5928.5,2200 5930.5,2202 v4(6020,2202)
  Layer 6 - Bottom Layer w5.9: J1.4@5828.33,992.46 5828.33,1060.71
  Layer 6 - Bottom Layer w10: J7.3@5765.98,2752.86 5705,2691.87 5705,2570 5815,2460 v4(5815,2200) ; 5828.33,1060.71 5828.33,1968.33 6020,2160 v4(6020,2202)
I2C_SDA_UB960: R68.1 U1.11 U2.11 U5.4 | length 6998.1
  Layer 1 - Top Layer w5: v4(2410,3848) 2413.21,3851.21 U2.11@2413.21,3875.77 ; v4(2987.56,1650.87) cw(c2999.21,1650.87) 2999.21,1662.52 U1.11@3013.35,1662.52
  Layer 1 - Top Layer w10: v4(2842.01,2429.45) 2842.01,2470.48 2952.71,2581.19 v4@2952.71,3002.93 ; R68.1@6235.31,1785.33 6237.09,1787.1 U5.4@6306.12,1787.1 ; v3(6244.69,1740.63) R68.1@6244.69,1785.63
  Layer 4 - Signal w5: v4(2410,3848) 2410,3805 2400,3795 2400,3375 2450,3325 v4(2515,3325)
  Layer 4 - Signal w10: v3(5321,2784) 5687.01,2417.99 5687.01,2017.72 5966.5,1738.22 v3@6242.97,1738.22 ; v3@6243.83,1741.5 v3(6244.69,1740.63)
  Layer 6 - Bottom Layer w5: v4@2841.69,2429.76 2772.56,2360.63 2772.56,1810.87 2827.56,1755.87 2947.56,1755.87 2977.56,1725.87 2977.56,1667.22 2987.56,1657.22 v4(2987.56,1650.87)
  Layer 6 - Bottom Layer w10: v4(2515,3325) 2631,3325 v4(2954,3002) 3172,2784 v3(5321,2784)
I2C_SDA_UC: J8.3 R55.1 R63.1 TP7.1 U4.7 U5.7 U6.7 | length 3474.3
  Layer 1 - Top Layer w5: U4.7@6027.56,2663.01 R55.1@6085.41,2663.01 ; R55.1@6092.36,2656.06 6120.57,2627.86 6250.98,2627.86 6385.98,2762.86 J8.3@6445.98,2762.86
  Layer 1 - Top Layer w10: v4(5655,3375) R63.1@5692.6,3375 ; U5.7@6359.27,1806.79 TP7.1@6569.41,1806.79 ; U6.7@6376.57,2260.16 v3(6544.84,2260.16) ; J8.3@6445.98,2762.86 6597.86,2762.86 v3(6597.86,2762.14) ; TP7.1@6571.03,1817.18 6571.03,1966.82 6601.13,1996.92 6601.13,2161.56 6601,2260.72 6600.34,2762.15 v3(6600,3015)
  Layer 4 - Signal w10: v4(5655,3375) 5905,3375 6010,3270 6010,3195 6080,3125 6525,3125 6600,3050 v3(6600,3015)
  Layer 6 - Bottom Layer w10: v3(6544.84,2260.16) 6600.2,2260.16 v3@6601.91,2258.44
  other v3: 6602.14,2260.72
I2C_SW_EXTERNAL: R45.1 R70.1 TP9.1 U3.5 U6.9 | length 2575.4
  Layer 1 - Top Layer w10: v3(5665,3535) 5653.62,3535 R45.1@5623.62,3565 5745,3565 5767.05,3542.95 U3.5@5885.39,3542.95 ; U6.9@6376.57,2299.53 6439.53,2299.53 6461.83,2321.83 6461.83,2423.18 6454.86,2430.15 ; 6454.82,2430.18 6454.82,2491.82 TP9.1@6498,2535
  Layer 1 - Top Layer w15: R70.1@6388.37,2430.18 6454.82,2430.18
  Layer 4 - Signal w10: v3(5665,3535) 5665,3465 5585,3385 5585,2710.28 5780.28,2515 6478,2515 TP9.1@6495,2532
I2C_SW_SOC: J6.1 R44.2 | length 201.4
  Layer 1 - Top Layer w10: R44.2@5223.62,3405 J6.1@5425,3405
I2C_SW_SOC_MSP430: R49.2 U3.3 | length 720.4
  Layer 1 - Top Layer w10: R49.2@5214.37,3475 5282.18,3475 5401.32,3594.13 U3.3@5885.39,3594.13
I2C_SW_SOC_OVERRIDE: R228.2 S3.2 | length 544.3
  Layer 1 - Top Layer w10: S3.2@4749.14,3170 4743,3163.86 4635,3163.86 4635,3267.41 4767.08,3399.49 R228.2@4904.38,3399.49
I2C_SW_SOC_TDA2XX: J1.20 R50.2 | length 4035.6
  Layer 1 - Top Layer w10: R50.2@5219.69,3540 v2(5265.9,3540)
  Layer 4 - Signal w10: v2(5265.9,3540) 5340.4,3614.5 5697,3614.5 5717.37,3594.13 6251.24,3594.13 v2(6426.75,3418.62)
  Layer 6 - Bottom Layer w10: J1.20@6064.55,992.46 6064.55,1151 5913.06,1302.5 5913.06,1968.92 6055,2110.87 6055,2451.93 6082.73,2479.66 6082.73,2780.73 6095,2793 6095,2867.86 6160.98,2933.84 6160.98,2988.98 6217,3045 6241.85,3045 6426.75,3229.9 v2(6426.75,3418.62) v2@6426.75,3418.88
I2C_SW_UB960: R46.1 R69.2 TP8.1 U3.6 U5.9 | length 2945.7
  Layer 1 - Top Layer w10: v4(5600,3475) R46.1@5600,3506.38 ; R46.1@5603.62,3510 5684.64,3510 5692,3517.36 5697.36,3517.36 5703,3523 5842.43,3523 5849.44,3515.98 U3.6@5865,3515.98 ; TP8.1@6052.06,1981.26 6129.28,2058.48 6413.65,2058.48 6466.34,2005.8 6466.34,1932.28 6448.2,1914.14 R69.2@6379.69,1914.14 6379.69,1855.63 6370.22,1846.16 U5.9@6359.27,1846.16
  Layer 4 - Signal w10: v4(5600,3475) 5561.02,3436.02 5561.02,2701.77 5738.37,2524.43 5738.37,2028.37 5849.79,1916.94 5992.07,1916.94 TP8.1@6055.67,1980.54
INTB_CAM: R186.1 U1.6 U3.32 | length 5314.9
  Layer 1 - Top Layer w5: v4(2985.56,1578.87) 3000.33,1564.09 U1.6@3013.35,1564.09
  Layer 1 - Top Layer w10: U3.32@6184.61,3491.77 6318.23,3491.77 6380,3430 v3(6380,3385)
  Layer 4 - Signal w5: v4(2985.56,1578.87) 2991.88,1572.54 v3(3629.92,1572.54)
  Layer 6 - Bottom Layer w10: v3(3629.92,1572.54) 3629.92,1575.79 3670.28,1616.14 3670.28,1643.7 3702.26,1675.69 3702.26,1716.04 4011.81,2025.59 5825.59,2025.59 5945,2145 5945,3010 6000,3065 6225,3065 6380,3220 v3(6380,3385) ; v3@6381.27,3383.59 6381.27,3405.13 6423.65,3447.51 6445.91,3447.51 6484.12,3409.29 R186.1@6484.12,3344.9
INTB_RADAR: R245.1 U2.6 U3.31 | length 5408.3
  Layer 1 - Top Layer w5: U2.6@2314.79,3875.77 2314.79,3891.79 v4(2328,3905)
  Layer 1 - Top Layer w10: U3.31@6184.61,3466.18 6185.79,3465 v3(6235,3465)
  Layer 4 - Signal w5: v4(2328,3905) 2323.23,3900.23 2323.23,3301.77 2375,3250 v4(2540,3250)
  Layer 6 - Bottom Layer w10: v4(2540,3250) 2699.28,3090.72 2699.28,3087.21 3014.35,2772.15 3017.85,2772.15 3177.13,2612.87 5332.87,2612.87 5830,3110 5915,3110 6160.52,3355.52 ; R245.1@6035.44,3403.18 6062.95,3403.18 6086.27,3379.85 6136.19,3379.85 6160.52,3355.52 ; v3(6235,3465) 6235,3430 6160.52,3355.52
LO: R114.1 U10.7 | length 167.6
  Layer 1 - Top Layer w10: U10.7@3566.18,5767.17 3590.59,5767.17 3675.08,5682.68 R114.1@3698.82,5682.68
LOL: R115.1 U10.8 | length 155.1
  Layer 1 - Top Layer w10: U10.8@3566.18,5786.85 3610.91,5786.85 3665.08,5732.68 R115.1@3698.82,5732.68
LPTX0_N: C102.1 U2.57 | length 132.1
  Layer 1 - Top Layer w5: C102.1@2067.62,4023.19 2086.37,4041.94 2187.99,4041.94 U2.57@2190.77,4039.16
LPTX0_P: C101.1 U2.56 | length 134.4
  Layer 1 - Top Layer w5: C101.1@2067.62,4073.19 2088.37,4052.44 2184.36,4052.44 U2.56@2190.77,4058.85
LPTX1_N: C41.1 U1.57 | length 130.4
  Layer 1 - Top Layer w3.94: U1.57@2849.96,1440.08 2844.64,1434.76 2844.64,1362.68 ccw(c2901.75,1362.68) 2861.37,1322.3 C41.1@2865.56,1318.11
LPTX1_P: C35.1 U1.56 | length 129.9
  Layer 1 - Top Layer w3.94: C35.1@2815.56,1318.11 2818.24,1320.79 ccw(c2776.35,1362.68) 2835.59,1362.68 2835.59,1434.76 U1.56@2830.27,1440.08
NetC19_1: C19.1 R21.1 R25.2 U1.46 | length 936.7
  Layer 1 - Top Layer w10: v4(2630.56,1511.87) 2637.39,1505.04 U1.46@2666.89,1505.04
  Layer 1 - Top Layer w20: R21.1@1967.56,1445.87 1967.56,1356.3 1969.37,1354.49 R25.2@2047.56,1354.49 ; R21.1@1968.94,1442.68 v4@1968.94,1477.52
  Layer 4 - Signal w10: v4(1967.56,1478.9) 2019.53,1530.87 2580.56,1530.87 2599.56,1511.87 v4(2630.56,1511.87)
NetC20_1: C20.1 R22.1 R26.1 U1.3 | length 888.7
  Layer 1 - Top Layer w5: U1.3@3013.35,1505.04 3036.85,1505.04 3044.56,1512.75 v4(3044.56,1515.87)
  Layer 1 - Top Layer w10: R26.1@3594.05,1383.34 3615.93,1361.46 v4(3648.15,1361.46) ; v4@3653.96,1355.88 3659.19,1350.65 C20.1@3705.6,1350.65 ; R22.1@3677.14,1260.96 3677.14,1325.13 C20.1@3678.93,1326.92
  Layer 4 - Signal w5: v4(3044.56,1515.87) 3472.56,1515.87 3626.97,1361.46 v4(3648.15,1361.46)
NetC26_1: C26.1 S4.1 S4.2 S4.3 S4.4 U1.45 | length 1950
  Layer 1 - Top Layer w10: S4.1@1367.56,876.74 S4.2@1417.56,876.74 ; v2(1392.56,1070.87) 1417.56,1045.87 S4.2@1417.56,876.74 ; C26.1@1518.8,776 1517.56,777.25 S4.4@1517.56,876.74 S4.3@1467.56,876.74 S4.2@1417.56,876.74 ; v4(2630.56,1539.87) 2645.7,1524.72 U1.45@2666.89,1524.72
  Layer 4 - Signal w10: v2(1392.56,1070.87) 1392.56,1088.4 1438.37,1134.21 1535.9,1134.21 1952.56,1550.87 2619.56,1550.87 v4(2630.56,1539.87)
NetC35_2: C35.2 R29.1 TP2.1 | length 96.3
  Layer 1 - Top Layer w3.94: TP2.1@2815.51,1174.49 C35.2@2815.51,1270.82
NetC41_2: C41.2 R29.2 TP1.1 | length 96.7
  Layer 1 - Top Layer w3.94: TP1.1@2864.33,1174.49 2864.33,1267.9 cw(c2868.52,1267.9) C41.2@2865.56,1270.87
NetC85_1: C85.1 R34.1 R38.2 U2.46 | length 830.7
  Layer 1 - Top Layer w5: U2.46@2255.73,4222.23 2255.73,4192.27 v4(2257,4191)
  Layer 1 - Top Layer w10: R34.1@2044,4731.38 2121.38,4731.38 2121.38,4785 R38.2@2116.38,4790 ; C85.1@2121.38,4728.62 2121.38,4682.12 2133.5,4670 2211.32,4670 2283,4598.32 v3(2283,4582)
  Layer 4 - Signal w5: v4(2257,4191) 2257,4239 2272,4254 2272,4307 2283,4318 v3(2283,4582)
NetC86_1: C86.1 R35.1 R39.1 U2.3 | length 1076.7
  Layer 1 - Top Layer w5: U2.3@2255.73,3875.77 2255.73,3904.06 v4(2256.67,3905)
  Layer 1 - Top Layer w10: R35.1@1976.09,2998.03 2031.13,2998.03 C86.1@2033.42,3000.32 ; C86.1@2048.93,3004.18 2048.93,3245.93 v4(2259,3456)
  Layer 4 - Signal w5: v4(2256.67,3905) 2256.67,3458.33 v4(2259,3456)
NetC95_1: C95.1 S5.1 S5.2 S5.3 S5.4 U2.45 | length 1451.4
  Layer 1 - Top Layer w5: U2.45@2275.42,4222.23 2275.42,4235.42 v4(2291,4251)
  Layer 1 - Top Layer w10: C95.1@2059.12,5324.2 S5.3@2136.31,5324.2 ; C95.1@2059.22,5319.43 2059.22,5162.72 2317.81,4904.13 2317.81,4857.4 ; S5.4@2136.31,5274.2 S5.3@2136.31,5324.2 ; S5.1@2136.31,5424.2 S5.2@2136.31,5374.2 S5.3@2136.31,5324.2 ; 2316.82,4856.41 2319,4854.23 v3(2319,4580)
  Layer 1 - Top Layer w30: C95.1@2057.74,5325.58 C95.1@2059.12,5324.2
  Layer 4 - Signal w5: v4(2291,4251) 2291,4279.5 2319,4307.5 v3(2319,4580)
NetC101_2: C101.2 R42.1 TP4.1 | length 106.4
  Layer 1 - Top Layer w5: TP4.1@1914,4073.19 C101.2@2020.38,4073.19
NetC102_2: C102.2 R42.2 TP3.1 | length 106.4
  Layer 1 - Top Layer w5: TP3.1@1914,4023.19 C102.2@2020.38,4023.19
NetC127_1: C127.1 R52.1 S2.1 U3.11 | length 1351.1
  Layer 1 - Top Layer w10: v3(5795,3400) 5805.59,3389.41 U3.11@5885.39,3389.41 ; v3(5960,3695) 5990,3695 6055,3760 6395,3760 6420,3785 6420,3853.62 C127.1@6465,3898.62 R52.1@6465,3966.38 6527.49,3966.38 S2.1@6570.98,4009.86
  Layer 6 - Bottom Layer w10: v3(5795,3400) 5914,3400 5915,3399 5960,3444 v3(5960,3695)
